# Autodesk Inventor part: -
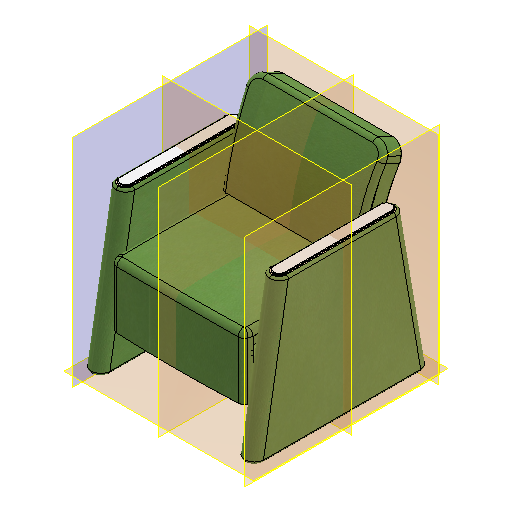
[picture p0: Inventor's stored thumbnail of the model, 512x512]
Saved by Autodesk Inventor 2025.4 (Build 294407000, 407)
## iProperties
Created: 2026-05
Part Number: -
Material: Generic
Description: BH CHAIR
Document SubType Name: Modeling
Designer: Brian.Thangei
Density: 1 g/cm^3
Appearance: Default
Project: SHORE
Sending System: SolidWorks 2026
Preprocessor: SwSTEP 2.0
Title: 1301.02 - SHORE BH CHAIR.STEP
Revision Number: ANY
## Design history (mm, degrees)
combine "NONE"
combine "NONE:1"
combine "NONE:2"
combine "NONE:3"
combine "NONE:4"
combine "NONE:5"
combine "NONE:6"
combine "NONE:7"
combine "NONE:8"
combine "NONE:9"
combine "NONE:10"
combine "NONE:11"
combine "NONE:12"
combine "NONE:13"
combine "NONE:14"
combine "Combine1"
combine "NONE:15"
combine "Combine3"
combine "Combine2"
  body "Solid14"
workplane "Work Plane1"
workplane "Work Plane2"
workplane "Work Plane4"
node "FOOT"
node "FOOT2"
node "FOOT3"
node "CORIAN"
node "FOOT4"
node "FOOT5"
node "CORIAN2"
node "ARM BASE"
node "FOOT6"
node "ARM BASE2"
node "ARM TOP"
node "ARM TOP 2"
node "SEAT"
node "BASE"
node "ARM"
node "ARM2"
node "BACK"
other parameters: "d0" = 0, "d1" = 0
